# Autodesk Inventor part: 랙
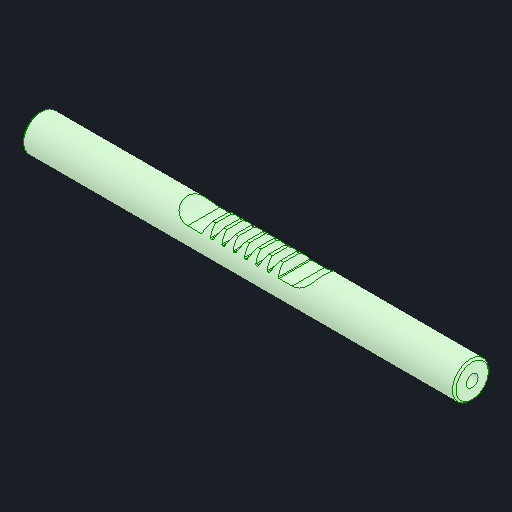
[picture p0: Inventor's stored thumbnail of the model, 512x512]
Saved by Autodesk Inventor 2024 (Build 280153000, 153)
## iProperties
Created: 2024-05
Part Number: 랙
Material: 강철, 탄소
Document SubType Name: Modeling
Designer: kh_501
Density: 7.85 g/cm^3
Appearance: 기본값
Author: jhkim
Sending System: Autodesk Inventor 2025
Preprocessor: ST-DEVELOPER v20
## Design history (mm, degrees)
feature "솔리드1"
node "솔리드2"
